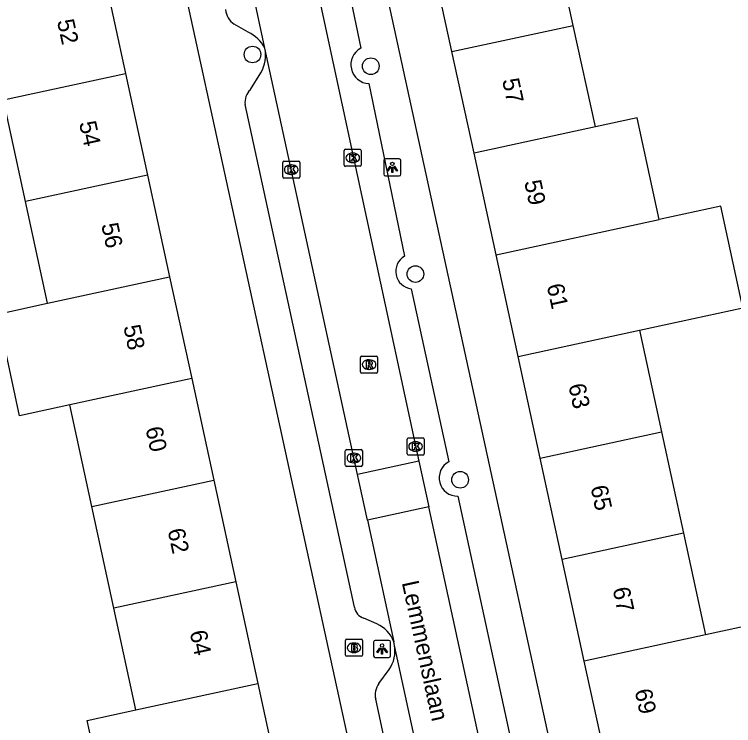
# Model space of a CAD drawing. Extents: x 159053 to 160041, y 380450 to 381422.
# Drawn here: x 159742.79 to 159785.02, y 380935.84 to 380977.59 of the extents above; entities that cross this region are included whole.
import ezdxf

# ---------------------------------------------------------------- set-up
doc = ezdxf.new("R2010")
doc.units = 0
for name, color, linetype in [('IMGEO_Boom', 7, 'Continuous'), ('IMGEO_Brandkraan', 7, 'Continuous'), ('IMGEO_Kolk', 7, 'Continuous'), ('IMGEO_Lichtpunt', 7, 'Continuous'), ('IMGEO_Openbare_ruimte_label', 7, 'Continuous'), ('IMGEO_Pand', 7, 'Continuous'), ('IMGEO_Pand_nummerreeks', 7, 'Continuous'), ('IMGEO_Rijbaan_lokaal_open', 7, 'Continuous'), ('IMGEO_Rioolput', 7, 'Continuous'), ('IMGEO_Voetpad_open', 7, 'Continuous')]:
    doc.layers.add(name, color=color, linetype=linetype)

msp = doc.modelspace()

# ---------------------------------------------------------------- linework, layer by layer
at = {"layer": 'IMGEO_Boom'}
for centre in [(159756.77, 380975.235), (159763.716, 380974.547), (159766.333, 380962.345), (159768.963, 380950.269)]:
    msp.add_circle(centre, 0.489, dxfattribs=at)
at = {"layer": 'IMGEO_Brandkraan'}
for p, q in [((159762.307, 380940.906), (159763.159, 380940.906)), ((159762.232, 380939.98), (159762.232, 380940.832)), ((159762.72, 380940.686), (159762.745, 380940.686)), ((159763.233, 380940.832), (159763.233, 380939.98)), ((159762.743, 380940.126), (159762.718, 380940.126)), ((159763.159, 380939.906), (159762.307, 380939.906))]:
    msp.add_line(p, q, dxfattribs=at)
for points in [[(159762.307, 380940.906), (159763.159, 380940.906)], [(159762.232, 380939.98), (159762.232, 380940.832)], [(159762.58, 380940.606), (159762.58, 380940.206), (159762.793, 380940.206)], [(159762.811, 380940.606), (159762.58, 380940.606)], [(159762.759, 380940.525), (159762.705, 380940.525), (159762.705, 380940.449)], [(159762.705, 380940.449), (159762.758, 380940.449)], [(159763.233, 380940.832), (159763.233, 380939.98)], [(159762.767, 380940.373), (159762.705, 380940.373), (159762.705, 380940.292)], [(159762.705, 380940.292), (159762.767, 380940.292)], [(159763.159, 380939.906), (159762.307, 380939.906)]]:
    msp.add_lwpolyline(points, dxfattribs=at)
for centre, radius, start, end in [((159762.309, 380940.83), 0.0765, 91.552, 178.448), ((159762.309, 380940.83), 0.0765, 91.552, 178.448), ((159763.157, 380940.83), 0.0765, 1.552, 88.448), ((159763.157, 380940.83), 0.0765, 1.552, 88.448), ((159762.76, 380940.487), 0.0379, 267.8285, 90.9355), ((159762.815, 380940.461), 0.145, 59.4692, 91.5367), ((159762.84, 380940.508), 0.0922, 285.5137, 58.1501), ((159762.768, 380940.332), 0.0404, 269.8759, 90.5077), ((159762.799, 380940.457), 0.251, 268.6676, 293.5347), ((159762.845, 380940.316), 0.105, 301.3115, 78.989), ((159762.309, 380939.982), 0.0765, 181.552, 268.448), ((159762.309, 380939.982), 0.0765, 181.552, 268.448), ((159763.157, 380939.982), 0.0765, 271.552, 358.448), ((159763.157, 380939.982), 0.0765, 271.552, 358.448)]:
    msp.add_arc(centre, radius, start, end, dxfattribs=at)
for centre, major_axis, ratio, start_param, end_param in [((159762.719, 380940.406), (-0.387, 0.002), 0.722429, 4.712389, 7.853982), ((159762.744, 380940.406), (-0.39, 0.002), 0.717154, 1.570796, 4.712389)]:
    msp.add_ellipse(centre, major_axis=major_axis, ratio=ratio, start_param=start_param, end_param=end_param, dxfattribs=at)
at = {"layer": 'IMGEO_Kolk'}
for p, q in [((159762.159, 380968.744), (159762.159, 380969.596)), ((159762.234, 380969.67), (159763.086, 380969.67)), ((159763.16, 380969.596), (159763.16, 380968.744)), ((159762.647, 380969.45), (159762.672, 380969.45)), ((159758.544, 380968.047), (159758.544, 380968.899)), ((159758.619, 380968.973), (159759.471, 380968.973)), ((159759.032, 380968.753), (159759.057, 380968.753)), ((159759.545, 380968.899), (159759.545, 380968.047)), ((159762.67, 380968.89), (159762.645, 380968.89)), ((159763.086, 380968.67), (159762.234, 380968.67)), ((159759.471, 380967.973), (159758.619, 380967.973)), ((159759.055, 380968.193), (159759.03, 380968.193)), ((159765.921, 380952.721), (159766.773, 380952.721)), ((159765.846, 380951.795), (159765.846, 380952.647)), ((159766.334, 380952.501), (159766.359, 380952.501)), ((159766.847, 380952.647), (159766.847, 380951.795)), ((159762.221, 380951.12), (159762.221, 380951.972)), ((159762.296, 380952.046), (159763.148, 380952.046)), ((159763.222, 380951.972), (159763.222, 380951.12)), ((159766.357, 380951.941), (159766.332, 380951.941)), ((159762.709, 380951.826), (159762.734, 380951.826)), ((159766.773, 380951.721), (159765.921, 380951.721)), ((159763.148, 380951.046), (159762.296, 380951.046)), ((159762.732, 380951.266), (159762.707, 380951.266))]:
    msp.add_line(p, q, dxfattribs=at)
for points in [[(159762.159, 380968.744), (159762.159, 380969.596)], [(159762.234, 380969.67), (159763.086, 380969.67)], [(159763.16, 380969.596), (159763.16, 380968.744)], [(159762.48, 380969.37), (159762.603, 380969.37), (159762.603, 380969.219), (159762.733, 380969.37), (159762.897, 380969.37), (159762.751, 380969.219), (159762.904, 380968.97), (159762.752, 380968.97), (159762.667, 380969.134), (159762.603, 380969.067), (159762.603, 380968.97), (159762.48, 380968.97), (159762.48, 380969.37)], [(159758.544, 380968.047), (159758.544, 380968.899)], [(159758.619, 380968.973), (159759.471, 380968.973)], [(159759.545, 380968.899), (159759.545, 380968.047)], [(159758.865, 380968.673), (159758.988, 380968.673), (159758.988, 380968.522), (159759.118, 380968.673), (159759.282, 380968.673), (159759.136, 380968.522), (159759.289, 380968.273), (159759.137, 380968.273), (159759.052, 380968.437), (159758.988, 380968.37), (159758.988, 380968.273), (159758.865, 380968.273), (159758.865, 380968.673)], [(159763.086, 380968.67), (159762.234, 380968.67)], [(159759.471, 380967.973), (159758.619, 380967.973)], [(159765.921, 380952.721), (159766.773, 380952.721)], [(159765.846, 380951.795), (159765.846, 380952.647)], [(159766.167, 380952.421), (159766.29, 380952.421), (159766.29, 380952.27), (159766.42, 380952.421), (159766.584, 380952.421), (159766.438, 380952.27), (159766.591, 380952.021), (159766.439, 380952.021), (159766.354, 380952.185), (159766.29, 380952.118), (159766.29, 380952.021), (159766.167, 380952.021), (159766.167, 380952.421)], [(159766.847, 380952.647), (159766.847, 380951.795)], [(159762.221, 380951.12), (159762.221, 380951.972)], [(159762.296, 380952.046), (159763.148, 380952.046)], [(159763.222, 380951.972), (159763.222, 380951.12)], [(159762.542, 380951.746), (159762.665, 380951.746), (159762.665, 380951.595), (159762.795, 380951.746), (159762.959, 380951.746), (159762.813, 380951.595), (159762.966, 380951.346), (159762.814, 380951.346), (159762.729, 380951.51), (159762.665, 380951.443), (159762.665, 380951.346), (159762.542, 380951.346), (159762.542, 380951.746)], [(159766.773, 380951.721), (159765.921, 380951.721)], [(159763.148, 380951.046), (159762.296, 380951.046)]]:
    msp.add_lwpolyline(points, dxfattribs=at)
for centre, start, end in [((159762.236, 380969.594), 91.552, 178.448), ((159762.236, 380969.594), 91.552, 178.448), ((159763.084, 380969.594), 1.552, 88.448), ((159763.084, 380969.594), 1.552, 88.448), ((159758.621, 380968.897), 91.552, 178.448), ((159758.621, 380968.897), 91.552, 178.448), ((159759.469, 380968.897), 1.552, 88.448), ((159759.469, 380968.897), 1.552, 88.448), ((159762.236, 380968.746), 181.552, 268.448), ((159762.236, 380968.746), 181.552, 268.448), ((159763.084, 380968.746), 271.552, 358.448), ((159763.084, 380968.746), 271.552, 358.448), ((159758.621, 380968.049), 181.552, 268.448), ((159758.621, 380968.049), 181.552, 268.448), ((159759.469, 380968.049), 271.552, 358.448), ((159759.469, 380968.049), 271.552, 358.448), ((159765.923, 380952.645), 91.552, 178.448), ((159765.923, 380952.645), 91.552, 178.448), ((159766.771, 380952.645), 1.552, 88.448), ((159766.771, 380952.645), 1.552, 88.448), ((159762.298, 380951.97), 91.552, 178.448), ((159762.298, 380951.97), 91.552, 178.448), ((159763.146, 380951.97), 1.552, 88.448), ((159763.146, 380951.97), 1.552, 88.448), ((159765.923, 380951.797), 181.552, 268.448), ((159765.923, 380951.797), 181.552, 268.448), ((159766.771, 380951.797), 271.552, 358.448), ((159766.771, 380951.797), 271.552, 358.448), ((159762.298, 380951.122), 181.552, 268.448), ((159762.298, 380951.122), 181.552, 268.448), ((159763.146, 380951.122), 271.552, 358.448), ((159763.146, 380951.122), 271.552, 358.448)]:
    msp.add_arc(centre, 0.0765, start, end, dxfattribs=at)
for centre, major_axis, ratio, start_param, end_param in [((159762.646, 380969.17), (-0.387, 0.002), 0.722429, 4.712389, 7.853982), ((159762.671, 380969.17), (-0.39, 0.002), 0.717154, 1.570796, 4.712389), ((159759.031, 380968.473), (-0.387, 0.002), 0.722429, 4.712389, 7.853982), ((159759.056, 380968.473), (-0.39, 0.002), 0.717154, 1.570796, 4.712389), ((159766.333, 380952.221), (-0.387, 0.002), 0.722429, 4.712389, 7.853982), ((159766.358, 380952.221), (-0.39, 0.002), 0.717154, 1.570796, 4.712389), ((159762.708, 380951.546), (-0.387, 0.002), 0.722429, 4.712389, 7.853982), ((159762.733, 380951.546), (-0.39, 0.002), 0.717154, 1.570796, 4.712389)]:
    msp.add_ellipse(centre, major_axis=major_axis, ratio=ratio, start_param=start_param, end_param=end_param, dxfattribs=at)
at = {"layer": 'IMGEO_Lichtpunt'}
for p, q in [((159764.483, 380969.013), (159764.483, 380968.206)), ((159764.483, 380969.013), (159764.483, 380968.206)), ((159765.385, 380969.108), (159764.577, 380969.108)), ((159765.385, 380969.108), (159764.577, 380969.108)), ((159765.479, 380968.206), (159765.479, 380969.013)), ((159765.479, 380968.206), (159765.479, 380969.013)), ((159764.577, 380968.112), (159765.385, 380968.112)), ((159764.577, 380968.112), (159765.385, 380968.112)), ((159763.878, 380940.742), (159763.878, 380939.935)), ((159763.878, 380940.742), (159763.878, 380939.935)), ((159764.78, 380940.837), (159763.972, 380940.837)), ((159764.78, 380940.837), (159763.972, 380940.837)), ((159764.874, 380939.935), (159764.874, 380940.742)), ((159764.874, 380939.935), (159764.874, 380940.742)), ((159763.972, 380939.841), (159764.78, 380939.841)), ((159763.972, 380939.841), (159764.78, 380939.841))]:
    msp.add_line(p, q, dxfattribs=at)
for points in [[(159764.857, 380968.677), (159764.896, 380968.649), (159764.708, 380968.387), (159764.67, 380968.414), (159764.857, 380968.677)], [(159764.959, 380968.629), (159765.006, 380968.629), (159765.006, 380968.307), (159764.959, 380968.307), (159764.959, 380968.629)], [(159765.069, 380968.649), (159765.107, 380968.676), (159765.294, 380968.414), (159765.255, 380968.386), (159765.069, 380968.649)], [(159764.252, 380940.406), (159764.291, 380940.378), (159764.103, 380940.116), (159764.065, 380940.143), (159764.252, 380940.406)], [(159764.354, 380940.358), (159764.401, 380940.358), (159764.401, 380940.036), (159764.354, 380940.036), (159764.354, 380940.358)], [(159764.464, 380940.378), (159764.502, 380940.405), (159764.689, 380940.143), (159764.65, 380940.115), (159764.464, 380940.378)]]:
    msp.add_lwpolyline(points, dxfattribs=at)
for centre in [(159764.982, 380968.811), (159764.377, 380940.54)]:
    msp.add_circle(centre, 0.0994, dxfattribs=at)
for centre, start, end in [((159764.577, 380969.013), 90, 180), ((159764.577, 380969.013), 90, 180), ((159765.385, 380969.013), 0, 90), ((159765.385, 380969.013), 0, 90), ((159764.577, 380968.206), 180, 270), ((159764.577, 380968.206), 180, 270), ((159765.385, 380968.206), 270, 0), ((159765.385, 380968.206), 270, 360), ((159763.972, 380940.742), 90, 180), ((159763.972, 380940.742), 90, 180), ((159764.78, 380940.742), 0, 90), ((159764.78, 380940.742), 0, 90), ((159763.972, 380939.935), 180, 270), ((159763.972, 380939.935), 180, 270), ((159764.78, 380939.935), 270, 0), ((159764.78, 380939.935), 270, 360)]:
    msp.add_arc(centre, 0.0946, start, end, dxfattribs=at)
at = {"layer": 'IMGEO_Pand'}
for points in [[(159775.607, 380976.947), (159774.312, 380982.91)], [(159768.483, 380975.402), (159767.188, 380981.365)], [(159748.013, 380980.089), (159749.309, 380974.122)], [(159768.483, 380975.402), (159775.607, 380976.947)], [(159776.903, 380970.982), (159775.607, 380976.947)], [(159769.779, 380969.437), (159768.483, 380975.402)], [(159742.145, 380972.566), (159749.309, 380974.122)], [(159749.309, 380974.122), (159750.606, 380968.153)], [(159743.441, 380966.598), (159742.145, 380972.566)], [(159780.65, 380965.55), (159779.357, 380971.514), (159776.903, 380970.982)], [(159776.903, 380970.982), (159769.779, 380969.437)], [(159771.074, 380963.473), (159769.779, 380969.437)], [(159750.606, 380968.153), (159743.441, 380966.598)], [(159750.606, 380968.153), (159751.902, 380962.186)], [(159744.737, 380960.63), (159743.441, 380966.598)], [(159779.494, 380959.055), (159781.944, 380959.586), (159785.561, 380960.371), (159784.267, 380966.335), (159780.65, 380965.55)], [(159771.074, 380963.473), (159780.65, 380965.55)], [(159772.37, 380957.51), (159771.074, 380963.473)], [(159744.737, 380960.63), (159751.902, 380962.186)], [(159751.902, 380962.186), (159753.199, 380956.218)], [(159746.034, 380954.663), (159743.095, 380954.025), (159741.799, 380959.992), (159744.737, 380960.63)], [(159772.37, 380957.51), (159779.494, 380959.055)], [(159779.494, 380959.055), (159780.79, 380953.09)], [(159773.665, 380951.545), (159772.37, 380957.51)], [(159753.199, 380956.218), (159746.034, 380954.663)], [(159753.199, 380956.218), (159754.495, 380950.25)], [(159747.33, 380948.695), (159746.034, 380954.663)], [(159773.665, 380951.545), (159780.79, 380953.09)], [(159780.79, 380953.09), (159782.085, 380947.126)], [(159774.961, 380945.582), (159773.665, 380951.545)], [(159747.33, 380948.695), (159754.495, 380950.25)], [(159754.495, 380950.25), (159755.791, 380944.282)], [(159748.627, 380942.727), (159747.33, 380948.695)], [(159782.085, 380947.126), (159774.961, 380945.582)], [(159782.085, 380947.126), (159783.38, 380941.164)], [(159776.256, 380939.618), (159774.961, 380945.582)], [(159755.791, 380944.282), (159748.627, 380942.727)], [(159755.791, 380944.282), (159757.088, 380938.314)], [(159749.923, 380936.76), (159748.627, 380942.727)], [(159784.676, 380935.199), (159790.506, 380936.463), (159790.832, 380936.537), (159790.377, 380938.63), (159787.933, 380938.1), (159787.094, 380941.969), (159783.38, 380941.164)], [(159783.38, 380941.164), (159776.256, 380939.618)], [(159777.552, 380933.654), (159776.256, 380939.618)], [(159749.923, 380936.76), (159757.088, 380938.314)], [(159757.088, 380938.314), (159758.384, 380932.346)], [(159748.367, 380930.172), (159747.613, 380933.639), (159747.069, 380936.14), (159749.923, 380936.76)]]:
    msp.add_lwpolyline(points, dxfattribs=at)
at = {"layer": 'IMGEO_Rijbaan_lokaal_open'}
for points in [[(159758.133, 380990.369), (159766.534, 380951.359)], [(159757.498, 380975.602), (159754.474, 380989.713)], [(159762.934, 380950.576), (159757.498, 380975.602)], [(159766.534, 380951.359), (159762.934, 380950.576)], [(159766.534, 380951.359), (159767.118, 380948.672)], [(159763.518, 380947.889), (159762.934, 380950.576)], [(159767.118, 380948.672), (159763.518, 380947.889)], [(159775.62, 380909.586), (159767.118, 380948.672)], [(159763.518, 380947.889), (159765.066, 380940.761)], [(159765.113, 380940.546), (159765.066, 380940.761)], [(159772.009, 380908.801), (159765.113, 380940.546)]]:
    msp.add_lwpolyline(points, dxfattribs=at)
at = {"layer": 'IMGEO_Rioolput'}
for p, q in [((159763.115, 380956.604), (159763.115, 380957.456)), ((159763.19, 380957.53), (159764.042, 380957.53)), ((159764.116, 380957.456), (159764.116, 380956.604)), ((159763.603, 380957.31), (159763.628, 380957.31)), ((159764.042, 380956.53), (159763.19, 380956.53)), ((159763.626, 380956.75), (159763.601, 380956.75))]:
    msp.add_line(p, q, dxfattribs=at)
for points in [[(159763.115, 380956.604), (159763.115, 380957.456)], [(159763.19, 380957.53), (159764.042, 380957.53)], [(159764.116, 380957.456), (159764.116, 380956.604)], [(159763.704, 380957.228), (159763.452, 380957.23), (159763.452, 380956.83)], [(159763.452, 380956.83), (159763.576, 380956.83), (159763.576, 380956.992), (159763.587, 380956.992)], [(159763.63, 380957.149), (159763.576, 380957.149), (159763.576, 380957.068)], [(159763.576, 380957.068), (159763.628, 380957.068)], [(159763.634, 380956.963), (159763.705, 380956.83), (159763.845, 380956.83), (159763.78, 380956.956)], [(159764.042, 380956.53), (159763.19, 380956.53)]]:
    msp.add_lwpolyline(points, dxfattribs=at)
for centre, radius, start, end in [((159763.192, 380957.454), 0.0765, 91.552, 178.448), ((159763.192, 380957.454), 0.0765, 91.552, 178.448), ((159764.04, 380957.454), 0.0765, 1.552, 88.448), ((159764.04, 380957.454), 0.0765, 1.552, 88.448), ((159763.586, 380956.939), 0.0533, 26.0293, 88.6989), ((159763.612, 380957.257), 0.19, 274.7715, 282.9687), ((159763.636, 380957.053), 0.0964, 77.0061, 93.1865), ((159763.65, 380957.11), 0.0378, 276.6634, 79.6772), ((159763.703, 380957.118), 0.109, 350.3612, 89.416), ((159763.701, 380957.118), 0.112, 277.5842, 350.9817), ((159763.685, 380956.903), 0.108, 29.5134, 73.7905), ((159763.192, 380956.606), 0.0765, 181.552, 268.448), ((159763.192, 380956.606), 0.0765, 181.552, 268.448), ((159764.04, 380956.606), 0.0765, 271.552, 358.448), ((159764.04, 380956.606), 0.0765, 271.552, 358.448)]:
    msp.add_arc(centre, radius, start, end, dxfattribs=at)
for centre, major_axis, ratio, start_param, end_param in [((159763.602, 380957.03), (-0.387, 0.002), 0.722429, 4.712389, 7.853982), ((159763.627, 380957.03), (-0.39, 0.002), 0.717154, 1.570796, 4.712389)]:
    msp.add_ellipse(centre, major_axis=major_axis, ratio=ratio, start_param=start_param, end_param=end_param, dxfattribs=at)
at = {"layer": 'IMGEO_Voetpad_open'}
for points in [[(159761.527, 380992.896), (159763.76, 380982.861), (159780.956, 380903.896)], [(159769.108, 380904.305), (159752.372, 380981.031), (159749.854, 380992.523)], [(159760.444, 380988.034), (159761.136, 380985.205), (159763.124, 380975.604)], [(159756.513, 380976.542), (159755.699, 380977.007)], [(159756.643, 380973.171), (159757.266, 380974.161)], [(159763.599, 380973.525), (159765.697, 380963.391)], [(159762.76, 380942.78), (159756.336, 380972.296)], [(159766.093, 380961.484), (159768.3, 380951.32)], [(159768.828, 380949.306), (159772.335, 380933.177)], [(159764.078, 380941.805), (159763.304, 380942.144)], [(159764.197, 380938.309), (159764.792, 380939.127)], [(159773.696, 380892.245), (159764.005, 380937.382)]]:
    msp.add_lwpolyline(points, dxfattribs=at)
for centre, radius, start, end in [((159756.396, 380978.013), 1.224, 186.5683, 235.3008), ((159755.598, 380974.598), 2.149, 27.8689, 64.8094), ((159755.402, 380975.2), 2.134, 330.8593, 10.8485), ((159763.654, 380974.631), 1.108, 118.5828, 267.1567), ((159757.373, 380972.423), 1.045, 134.3306, 187.0019), ((159766.203, 380962.501), 1.023, 119.6274, 263.8348), ((159768.798, 380950.374), 1.069, 117.7558, 271.6249), ((159763.564, 380942.917), 0.815, 189.6499, 251.4339), ((159763.351, 380940.127), 1.829, 20.2806, 66.5621), ((159763.192, 380940.235), 1.946, 325.3043, 9.2023), ((159765.062, 380937.646), 1.09, 142.5561, 194.0406)]:
    msp.add_arc(centre, radius, start, end, dxfattribs=at)

# ---------------------------------------------------------------- texts
at = {"layer": 'IMGEO_Openbare_ruimte_label'}
msp.add_text('Lemmenslaan', height=1, rotation=282.2989, dxfattribs=at).set_placement((159765.532, 380944.234))
at = {"layer": 'IMGEO_Pand_nummerreeks'}
for s, rotation, p in [('52', 282.2553, (159745.284, 380977.203)), ('57', 282.2554, (159771.423, 380973.736)), ('54', 282.2553, (159746.582, 380971.222)), ('59', 282.2554, (159772.721, 380967.762)), ('56', 282.2553, (159747.881, 380965.244)), ('61', 282.2554, (159774.044, 380961.678)), ('58', 282.2553, (159749.181, 380959.262)), ('63', 282.2554, (159775.317, 380955.814)), ('60', 282.2553, (159750.479, 380953.284)), ('65', 282.2554, (159776.614, 380949.839)), ('62', 282.2553, (159751.777, 380947.312)), ('67', 282.2554, (159777.912, 380943.865)), ('64', 282.2553, (159753.075, 380941.331)), ('69', 282.2554, (159779.21, 380937.891))]:
    msp.add_text(s, height=1, rotation=rotation, dxfattribs=at).set_placement(p)

doc.saveas('drawing.dxf')
